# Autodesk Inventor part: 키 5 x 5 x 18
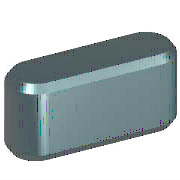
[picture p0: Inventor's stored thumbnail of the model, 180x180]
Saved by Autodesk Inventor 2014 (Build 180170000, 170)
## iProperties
IsCustomPart: 1
Created: 2012-02
Part Number: 키 5 x 5 x 18
Material: 강철, 연강
Description: 키 및 해당 키홈
Document SubType Name: Modeling
Standard: KS B 1311
Designer: mduedu
Standards Organization: KS
Language: ko-KR
Size Designation: 5 x 5 x 18
Categories: <MemberInstance><Categories><Category DisplayName="샤프트 부품" InternalName="7f7aeb1f-a693-4053-b835-cee3144e0d98" Mnemonic="SHFT"><Category DisplayName="키" Interna
Density: 7.86 g/cm^3
Appearance: Gold
Mass: 3.27476 g
Surface Area: 3.57848 cm^2
Volume: 0.416636 cm^3
Author: mduedu
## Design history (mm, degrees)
sketch "스케치1"
  geometry: L1 (2.5, 2.5)-(15.5, 2.5); L2 (15.5, -2.5)-(2.5, -2.5); L3 (0, 9.4)-(0, -7.4) reference; L4 (-5, 0)-(30, 0) reference; L5 (18, 0)-(18, 7); A1 r 2.5 centre (2.5, 0) between (2.5, 2.5) and (2.5, -2.5); A2 r 2.5 centre (15.5, 0) between (15.5, -2.5) and (15.5, 2.5)
  constraints: 6 end point, 5 point on circle, 4 tangent, 3 point on line, 2 centre point, 1 horizontal, 1 parallel, 1 perpendicular
  dimensions: "d0" = 2.5 radius of A1 (= 0.5 x PB); "d13" = 2.5 radius of A2 (= 0.5 x PB); "d14" = 18 distance between parallel lines of L5 L3 (= NLG)
extrude "본체1" new body sketch "스케치1" taper "d3" = 0 deg; stored distance "d4" = 10
workplane "Work Plane3"
body "Solid1"
workplane "Work Plane1"
workplane "Work Plane2"
chamfer "모따기1" distance "d8" = 0.4 (= PHH); stored, may be unused: second distance "d9" = 0.4 (= PHH), angle "d15" = 45 deg
other parameters: "d1" = -3 (= -PNT), "d2" = 2 (= PH - PNT), "NLG" = 18 [user parameter; used in 3 equation terms], "PB" = 5 [user parameter; used in 2 equation terms], "PNT" = 3 [user parameter; used in 2 equation terms], "PH" = 5 [user parameter; used in 1 equation term], "PHH" = 0.4 [user parameter; used in 2 equation terms], "d10" = 0, "d16" = 0, "d17" = 0, "d18" = 0, "WDMIN" = 12 [user parameter], "PLB2" = 18 (= NLG) [user parameter], "WDMAX" = 17 [user parameter], "PLB1" = 18 (= NLG) [user parameter], "RR" = 0.16 [user parameter], "PUEB" = 2.3 [user parameter]
